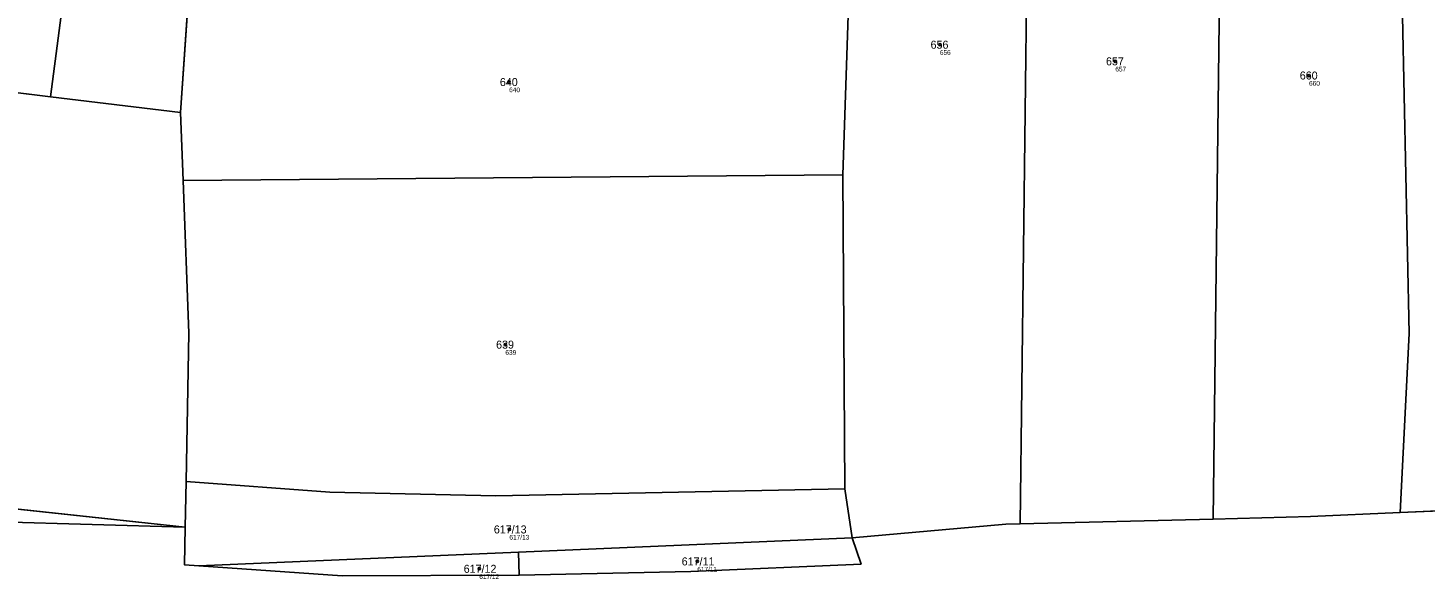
# Model space of a CAD drawing. Extents: x -767985 to -763816, y -1059600 to -1057360.
# Drawn here: x -764998 to -764701.2, y -1059401.4 to -1059284.4 of the extents above; entities that cross this region are included whole.
import ezdxf

# ---------------------------------------------------------------- set-up
doc = ezdxf.new("R2010")
doc.units = 0
for name, color, linetype in [('Definiční body', 7, 'Continuous'), ('Hranice parcel', 7, 'Continuous'), ('Parcelní čísla', 7, 'Continuous'), ('Polygon ku', 7, 'Continuous'), ('Polygon parcely', 7, 'Continuous')]:
    doc.layers.add(name, color=color, linetype=linetype)

msp = doc.modelspace()

# ---------------------------------------------------------------- linework, layer by layer
at = {"layer": 'Definiční body'}
for centre in [(-764804.29, -1059287.98994), (-764767.03, -1059291.51994), (-764895.76, -1059295.91994), (-764725.88, -1059294.52994), (-764896.56, -1059351.64994), (-764895.71, -1059390.86994), (-764902.11, -1059399.22994), (-764855.81, -1059397.65994)]:
    msp.add_circle(centre, 0.25, dxfattribs=at)
at = {"layer": 'Hranice parcel'}
for p, q in [((-764963.4, -1059271.33), (-764965.58, -1059302.41)), ((-764824.88, -1059315.59), (-764823.73, -1059281.76)), ((-764993.16, -1059299.02), (-765074.87, -1059288.96)), ((-764965.58, -1059302.41), (-764993.16, -1059299.02)), ((-764965.02, -1059316.8), (-764965.58, -1059302.41)), ((-764824.88, -1059315.59), (-764965.02, -1059316.8)), ((-764824.47, -1059382.24), (-764824.88, -1059315.59)), ((-765071.95, -1059378.89), (-764964.54, -1059390.4)), ((-764964.54, -1059390.4), (-764964.36, -1059380.68)), ((-764822.93, -1059392.66), (-764824.47, -1059382.24)), ((-764664.49, -1059385.45), (-764706.52, -1059387.29)), ((-764964.68, -1059398.41), (-764964.54, -1059390.4)), ((-764790.27, -1059389.78), (-764822.93, -1059392.66)), ((-764787.27, -1059389.7), (-764790.27, -1059389.78)), ((-764746.26, -1059388.66), (-764787.27, -1059389.7)), ((-764822.93, -1059392.66), (-764893.81, -1059395.71)), ((-764822.93, -1059392.66), (-764821.02, -1059398.24)), ((-764893.81, -1059395.71), (-764961.64, -1059398.62)), ((-764893.81, -1059395.71), (-764893.65, -1059400.56)), ((-764961.64, -1059398.62), (-764964.68, -1059398.41))]:
    msp.add_line(p, q, dxfattribs=at)
for points in [[(-764993.16, -1059299.02), (-764986.03, -1059244.31), (-764978.64, -1059200.79), (-764969.08, -1059151.21)], [(-764787.27, -1059389.7), (-764785.79, -1059273), (-764778.67, -1059205.63)], [(-764746.26, -1059388.66), (-764744.72, -1059259.5), (-764740.92, -1059208.29)], [(-764706.52, -1059387.29), (-764704.63, -1059349.3), (-764707.42, -1059214.53)], [(-764964.36, -1059380.68), (-764963.77, -1059349.23), (-764965.02, -1059316.8)], [(-764824.47, -1059382.24), (-764898.59, -1059383.77), (-764933.82, -1059382.99), (-764964.36, -1059380.68)], [(-764964.54, -1059390.4), (-765043.67, -1059388.12), (-765072.34, -1059384.05)], [(-764706.52, -1059387.29), (-764725.57, -1059388.13), (-764746.26, -1059388.66)], [(-764893.65, -1059400.56), (-764931.25, -1059400.73), (-764961.64, -1059398.62)], [(-764821.02, -1059398.24), (-764857.18, -1059399.8), (-764893.65, -1059400.56)]]:
    msp.add_lwpolyline(points, dxfattribs=at)
at = {"layer": 'Polygon ku'}
msp.add_lwpolyline([(-765043.67, -1059388.12), (-764964.54, -1059390.4), (-764964.68, -1059398.41), (-764961.64, -1059398.62), (-764931.25, -1059400.73), (-764893.65, -1059400.56), (-764857.18, -1059399.8), (-764821.02, -1059398.24), (-764822.93, -1059392.66), (-764790.27, -1059389.78), (-764787.27, -1059389.7), (-764746.26, -1059388.66), (-764725.57, -1059388.13), (-764706.52, -1059387.29), (-764664.49, -1059385.45), (-764661.48, -1059343.79), (-764625.54, -1059342.27), (-764569.63, -1059339.9), (-764563.36, -1059340.15), (-764557.81, -1059340.38), (-764557.37, -1059352.47), (-764555.46, -1059378.83), (-764481.18, -1059376.08)], dxfattribs=at)
at = {"layer": 'Polygon parcely'}
for points in [[(-764993.16, -1059299.02), (-764986.03, -1059244.31), (-764978.64, -1059200.79), (-764969.08, -1059151.21), (-765001.55, -1059136.08), (-765045.15, -1059110.12), (-765052, -1059130.58), (-765061.13, -1059169.33), (-765065.58, -1059198.93), (-765074.87, -1059288.96)], [(-764993.16, -1059299.02), (-764965.58, -1059302.41), (-764963.4, -1059271.33), (-764957.28, -1059228.13), (-764945.3, -1059159.91), (-764969.08, -1059151.21), (-764978.64, -1059200.79), (-764986.03, -1059244.31)], [(-764778.67, -1059205.63), (-764815.46, -1059201.74), (-764820.28, -1059238.28), (-764823.73, -1059281.76), (-764824.88, -1059315.59), (-764824.47, -1059382.24), (-764822.93, -1059392.66), (-764790.27, -1059389.78), (-764787.27, -1059389.7), (-764785.79, -1059273)], [(-764746.26, -1059388.66), (-764744.72, -1059259.5), (-764740.92, -1059208.29), (-764778.67, -1059205.63), (-764785.79, -1059273), (-764787.27, -1059389.7)], [(-764706.52, -1059387.29), (-764704.63, -1059349.3), (-764707.42, -1059214.53), (-764740.92, -1059208.29), (-764744.72, -1059259.5), (-764746.26, -1059388.66), (-764725.57, -1059388.13)], [(-764653.51, -1059223.97), (-764707.42, -1059214.53), (-764704.63, -1059349.3), (-764706.52, -1059387.29), (-764664.49, -1059385.45), (-764661.48, -1059343.79), (-764625.54, -1059342.27), (-764629.14, -1059225.48)], [(-764824.88, -1059315.59), (-764823.73, -1059281.76), (-764897.51, -1059273.71), (-764960.13, -1059271.45), (-764963.4, -1059271.33), (-764965.58, -1059302.41), (-764965.02, -1059316.8)], [(-764965.02, -1059316.8), (-764965.58, -1059302.41), (-764993.16, -1059299.02), (-765074.87, -1059288.96), (-765081.02, -1059348.55), (-765071.67, -1059352.09), (-765070.43, -1059358.81), (-765071.95, -1059378.89), (-764964.54, -1059390.4), (-764964.36, -1059380.68), (-764963.77, -1059349.23)], [(-764824.47, -1059382.24), (-764824.88, -1059315.59), (-764965.02, -1059316.8), (-764963.77, -1059349.23), (-764964.36, -1059380.68), (-764933.82, -1059382.99), (-764898.59, -1059383.77)], [(-765072.34, -1059384.05), (-765043.67, -1059388.12), (-764964.54, -1059390.4), (-765071.95, -1059378.89)], [(-764898.59, -1059383.77), (-764933.82, -1059382.99), (-764964.36, -1059380.68), (-764964.54, -1059390.4), (-764964.68, -1059398.41), (-764961.64, -1059398.62), (-764893.81, -1059395.71), (-764822.93, -1059392.66), (-764824.47, -1059382.24)], [(-764893.81, -1059395.71), (-764893.65, -1059400.56), (-764857.18, -1059399.8), (-764821.02, -1059398.24), (-764822.93, -1059392.66)], [(-764961.64, -1059398.62), (-764931.25, -1059400.73), (-764893.65, -1059400.56), (-764893.81, -1059395.71)]]:
    msp.add_lwpolyline(points, close=True, dxfattribs=at)

# ---------------------------------------------------------------- texts
at = {"layer": 'Definiční body'}
for s, p in [('656', (-764804.29, -1059290.146)), ('657', (-764767.03, -1059293.676)), ('660', (-764725.88, -1059296.686)), ('640', (-764895.76, -1059298.076)), ('639', (-764896.56, -1059353.806)), ('617/13', (-764895.71, -1059393.026)), ('617/11', (-764855.81, -1059399.816)), ('617/12', (-764902.11, -1059401.386))]:
    msp.add_text(s, height=0.999996, dxfattribs=at).set_placement(p)
at = {"layer": 'Parcelní čísla'}
for s, p in [('656', (-764806.264, -1059288.84)), ('657', (-764769.004, -1059292.37)), ('640', (-764897.734, -1059296.77)), ('660', (-764727.854, -1059295.38)), ('639', (-764898.534, -1059352.5)), ('617/13', (-764899.015, -1059391.72)), ('617/11', (-764859.115, -1059398.51)), ('617/12', (-764905.415, -1059400.08))]:
    msp.add_text(s, height=1.699998, dxfattribs=at).set_placement(p)

doc.saveas('drawing.dxf')
